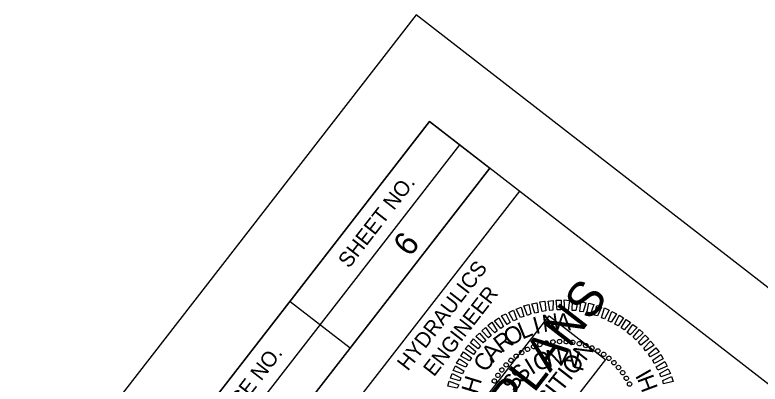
# Model space of a CAD drawing. Extents: x 2013373 to 2015284, y 444618 to 446636.
# Drawn here: x 2014282.4 to 2014527.7, y 446513.9 to 446635.5 of the extents above; entities that cross this region are included whole.
import ezdxf

# ---------------------------------------------------------------- set-up
doc = ezdxf.new("R2010")
doc.units = 0
for name, color, linetype in [('Old_Level_15', 7, 'Continuous'), ('Prop Conc 1ft 6in Curb and Gutter', 7, 'Continuous'), ('Prop Conc 2ft 9in Curb and Gutter', 7, 'Continuous'), ('Prop Conc 5in Monolithic Keyed In Island', 7, 'Continuous'), ('Prop Horizontal Alignment', 7, 'Continuous'), ('Prop Horizontal Alignment Tick Large', 7, 'Continuous')]:
    doc.layers.add(name, color=color, linetype=linetype)

msp = doc.modelspace()

# ---------------------------------------------------------------- linework, layer by layer
at = {"layer": 'Old_Level_15'}
for p, q in [((2014455.23, 446526.97), (2014455.23, 446526.97)), ((2014457.37, 446527.53), (2014457.37, 446527.53)), ((2014459.5, 446527.84), (2014459.5, 446527.84)), ((2014461.72, 446528.01), (2014461.72, 446528.01)), ((2014463.87, 446527.93), (2014463.87, 446527.93)), ((2014466.08, 446527.67), (2014466.08, 446527.67)), ((2014468.23, 446527.26), (2014468.23, 446527.26)), ((2014470.3, 446526.67), (2014470.3, 446526.67)), ((2014449.21, 446524.36), (2014449.21, 446524.36)), ((2014451.15, 446525.39), (2014451.15, 446525.39)), ((2014453.14, 446526.32), (2014453.14, 446526.32)), ((2014472.33, 446525.86), (2014472.33, 446525.86)), ((2014474.31, 446524.83), (2014474.31, 446524.83)), ((2014445.73, 446521.75), (2014445.73, 446521.75)), ((2014447.37, 446523.13), (2014447.37, 446523.13)), ((2014476.2, 446523.75), (2014476.2, 446523.75)), ((2014477.97, 446522.44), (2014477.97, 446522.44)), ((2014444.14, 446520.26), (2014444.14, 446520.26)), ((2014479.61, 446520.97), (2014479.61, 446520.97)), ((2014481.1, 446519.38), (2014481.1, 446519.38)), ((2014441.36, 446516.85), (2014441.36, 446516.85)), ((2014442.67, 446518.62), (2014442.67, 446518.62)), ((2014482.48, 446517.73), (2014482.48, 446517.73)), ((2014440.28, 446514.96), (2014440.28, 446514.96)), ((2014483.71, 446515.89), (2014483.71, 446515.89)), ((2014484.74, 446513.96), (2014484.74, 446513.96))]:
    msp.add_line(p, q, dxfattribs=at)
for points in [[(2014458.45, 446538.14), (2014457.91, 446541.28), (2014459.59, 446541.5), (2014459.54, 446538.25)], [(2014460.94, 446538.42), (2014460.57, 446541.62), (2014462.28, 446541.62), (2014462.16, 446538.36)], [(2014463.4, 446538.41), (2014463.24, 446541.64), (2014464.97, 446541.5), (2014464.52, 446538.31)], [(2014465.82, 446538.19), (2014465.94, 446541.44), (2014467.71, 446541.28), (2014467.04, 446538.13)], [(2014448.87, 446535.83), (2014447.44, 446538.64), (2014449.04, 446539.31), (2014449.93, 446536.21)], [(2014451.13, 446536.54), (2014449.91, 446539.7), (2014451.54, 446540.09), (2014452.28, 446537.04)], [(2014453.57, 446537.24), (2014452.53, 446540.39), (2014454.2, 446540.74), (2014454.71, 446537.56)], [(2014455.96, 446537.79), (2014455.16, 446541.01), (2014456.85, 446541.22), (2014457.14, 446538.09)], [(2014468.35, 446537.86), (2014468.69, 446541.15), (2014470.31, 446540.71), (2014469.47, 446537.76)], [(2014470.67, 446537.34), (2014471.29, 446540.59), (2014472.95, 446540.12), (2014471.84, 446537.06)], [(2014473.07, 446536.61), (2014473.92, 446539.81), (2014475.48, 446539.3), (2014474.21, 446536.36)], [(2014475.46, 446535.77), (2014476.51, 446539), (2014478, 446538.23), (2014476.51, 446535.4)], [(2014444.42, 446533.52), (2014442.64, 446536.36), (2014443.97, 446537.1), (2014445.4, 446534.21)], [(2014446.55, 446534.72), (2014444.99, 446537.51), (2014446.49, 446538.31), (2014447.66, 446535.25)], [(2014477.73, 446534.77), (2014478.91, 446537.84), (2014480.43, 446537.04), (2014478.74, 446534.37)], [(2014479.9, 446533.66), (2014481.34, 446536.65), (2014482.77, 446535.73), (2014480.97, 446533.08)], [(2014440.35, 446530.8), (2014438.09, 446533.18), (2014439.44, 446534.28), (2014441.19, 446531.47)], [(2014442.33, 446532.29), (2014440.34, 446534.79), (2014441.69, 446535.7), (2014443.25, 446532.91)], [(2014481.98, 446532.42), (2014483.65, 446535.24), (2014485.06, 446534.27), (2014482.99, 446531.77)], [(2014438.35, 446529.12), (2014436.1, 446531.43), (2014437.31, 446532.58), (2014439.2, 446529.97)], [(2014483.98, 446530.93), (2014485.86, 446533.59), (2014487.2, 446532.55), (2014484.93, 446530.2)], [(2014485.93, 446529.36), (2014488, 446531.87), (2014489.24, 446530.78), (2014486.82, 446528.54)], [(2014436.56, 446527.47), (2014434.12, 446529.62), (2014435.37, 446530.74), (2014437.46, 446528.29)], [(2014487.67, 446527.69), (2014489.87, 446530.04), (2014491.09, 446528.84), (2014488.47, 446526.76)], [(2014433.4, 446523.72), (2014430.68, 446525.51), (2014431.73, 446526.78), (2014434.18, 446524.63)], [(2014434.91, 446525.58), (2014432.34, 446527.57), (2014433.39, 446528.85), (2014435.69, 446526.5)], [(2014489.44, 446525.81), (2014491.66, 446528.02), (2014492.79, 446526.7), (2014490.03, 446524.85)], [(2014432.07, 446521.59), (2014429.2, 446523.11), (2014430.09, 446524.58), (2014432.68, 446522.63)], [(2014490.94, 446523.83), (2014493.35, 446525.88), (2014494.44, 446524.59), (2014491.53, 446522.87)], [(2014430.83, 446519.51), (2014427.81, 446520.84), (2014428.71, 446522.23), (2014431.45, 446520.55)], [(2014492.38, 446521.76), (2014494.99, 446523.66), (2014495.82, 446522.2), (2014492.87, 446520.69)], [(2014429.8, 446517.27), (2014426.66, 446518.37), (2014427.43, 446519.93), (2014430.24, 446518.26)], [(2014493.5, 446519.63), (2014496.31, 446521.37), (2014497.08, 446519.83), (2014494.07, 446518.56)], [(2014428.84, 446514.98), (2014425.76, 446515.91), (2014426.36, 446517.41), (2014429.21, 446516.02)], [(2014494.71, 446517.43), (2014497.44, 446518.91), (2014498.21, 446517.37), (2014495.09, 446516.37)], [(2014427.97, 446512.55), (2014424.88, 446513.3), (2014425.33, 446514.86), (2014428.5, 446513.72)], [(2014495.67, 446515.16), (2014498.57, 446516.45), (2014499.07, 446514.81), (2014495.89, 446513.98)]]:
    msp.add_lwpolyline(points, close=True, dxfattribs=at)
for centre, major_axis in [((2014453.16, 446526.26), (-0.26, 0.671)), ((2014455.23, 446526.96), (-0.201, 0.691)), ((2014457.36, 446527.48), (-0.14, 0.706)), ((2014459.52, 446527.81), (-0.078, 0.716)), ((2014461.7, 446527.95), (-0.015, 0.72)), ((2014463.89, 446527.9), (0.048, 0.718)), ((2014466.06, 446527.66), (0.11, 0.712)), ((2014468.21, 446527.24), (0.172, 0.699)), ((2014470.31, 446526.62), (0.232, 0.682)), ((2014449.23, 446524.33), (-0.373, 0.616)), ((2014451.15, 446525.38), (-0.318, 0.646)), ((2014472.35, 446525.83), (0.29, 0.659)), ((2014474.31, 446524.86), (0.347, 0.631)), ((2014476.18, 446523.72), (0.4, 0.598)), ((2014445.71, 446521.75), (-0.474, 0.542)), ((2014447.41, 446523.12), (-0.425, 0.581)), ((2014477.94, 446522.43), (0.451, 0.561)), ((2014479.59, 446520.98), (0.498, 0.52)), ((2014442.68, 446518.59), (-0.561, 0.451)), ((2014444.13, 446520.24), (-0.52, 0.498)), ((2014481.1, 446519.4), (0.542, 0.474)), ((2014441.39, 446516.83), (-0.598, 0.4)), ((2014482.47, 446517.69), (0.581, 0.425)), ((2014440.25, 446514.96), (-0.631, 0.347)), ((2014483.68, 446515.87), (0.616, 0.373)), ((2014484.73, 446513.95), (0.646, 0.318))]:
    msp.add_ellipse(centre, major_axis=major_axis, ratio=0.999708, dxfattribs=at)
at = {"layer": 'Prop Conc 5in Monolithic Keyed In Island'}
msp.add_lwpolyline([(2014241.91, 444618.03), (2015283.73, 445961.39), (2014414.5, 446635.51), (2013372.67, 445292.15)], close=True, dxfattribs=at)
at = {"layer": 'Prop Horizontal Alignment'}
for p, q in [((2014306.25, 446434.66), (2014428.85, 446592.74)), ((2014316.13, 446427), (2014438.73, 446585.08)), ((2014373.01, 446541.14), (2014392.76, 446525.82))]:
    msp.add_line(p, q, dxfattribs=at)
for points in [[(2014418.93, 446600.43), (2013499.68, 445415.12), (2014329.4, 444771.64), (2015248.65, 445956.96)], [(2014296.33, 446442.35), (2014418.93, 446600.43), (2014438.73, 446585.08), (2014316.13, 446427)], [(2014387.32, 446498.4), (2014448.6, 446577.42), (2014537.5, 446508.48), (2014476.22, 446429.46)]]:
    msp.add_lwpolyline(points, close=True, dxfattribs=at)
at = {"layer": 'Prop Horizontal Alignment Tick Large'}
msp.add_lwpolyline([(2014386.73, 446405.85), (2014368.16, 446420.25), (2014458.24, 446536.41), (2014476.81, 446522.01)], close=True, dxfattribs=at)

# ---------------------------------------------------------------- texts
at = {"layer": 'Old_Level_15'}
for s, rotation, p in [('N', 8.024, (2014456.35, 446531.04)), ('A', 0.8223, (2014460.49, 446531.56)), ('L', 22.426, (2014449.43, 446528.56)), ('I', 15.2252, (2014453.81, 446530.29)), ('O', 29.6263, (2014445.27, 446526.22)), ('R', 36.8262, (2014442.63, 446524.03)), ('C', 58.425, (2014437.71, 446517.53)), ('A', 51.2254, (2014439.9, 446520.83)), ('O', 22.0386, (2014454.33, 446517.99)), ('N', 12.6817, (2014457.97, 446519.41)), ('A', 353.9654, (2014461.77, 446520.07)), ('L', 344.606, (2014465.69, 446519.49)), ('I', 31.3947, (2014452.55, 446516.84)), ('S', 50.1055, (2014449.36, 446513.87)), ('S', 59.4607, (2014447.2, 446510.99)), ('H', 72.8246, (2014434.64, 446510.3))]:
    msp.add_text(s, height=5.64, rotation=rotation, dxfattribs=at).set_placement(p)
at = {"layer": 'Prop Conc 1ft 6in Curb and Gutter'}
msp.add_text('6', height=7.75, rotation=52.2051, dxfattribs=at).set_placement((2014412.46, 446555.53))
at = {"layer": 'Prop Conc 2ft 9in Curb and Gutter'}
for s, rotation, p in [('I', 119.7977, (2014492.21, 446517.66)), ('H', 110.5529, (2014494.2, 446512.65))]:
    msp.add_text(s, height=5.5, rotation=rotation, dxfattribs=at).set_placement(p)
at = {"layer": 'Prop Horizontal Alignment'}
for s, height, p in [('SHEET NO.', 5, (2014392.36, 446551.82)), ('HYDRAULICS', 5, (2014411.75, 446517.99)), ('ENGINEER', 5, (2014420.36, 446516.12)), ('PROJECT REFERENCE NO.', 5.0001, (2014316.81, 446454.56))]:
    msp.add_text(s, height=height, rotation=52.2051, dxfattribs=at).set_placement(p)
at = {"layer": 'Prop Horizontal Alignment Tick Large'}
for s, height, p in [('INCOMPLETE PLANS', 11.52, (2014382.97, 446420.09)), ('DO NOT USE FOR R/W ACQUISITION', 5.76, (2014390.45, 446418.4))]:
    msp.add_text(s, height=height, rotation=52.2051, dxfattribs=at).set_placement(p)

doc.saveas('drawing.dxf')
